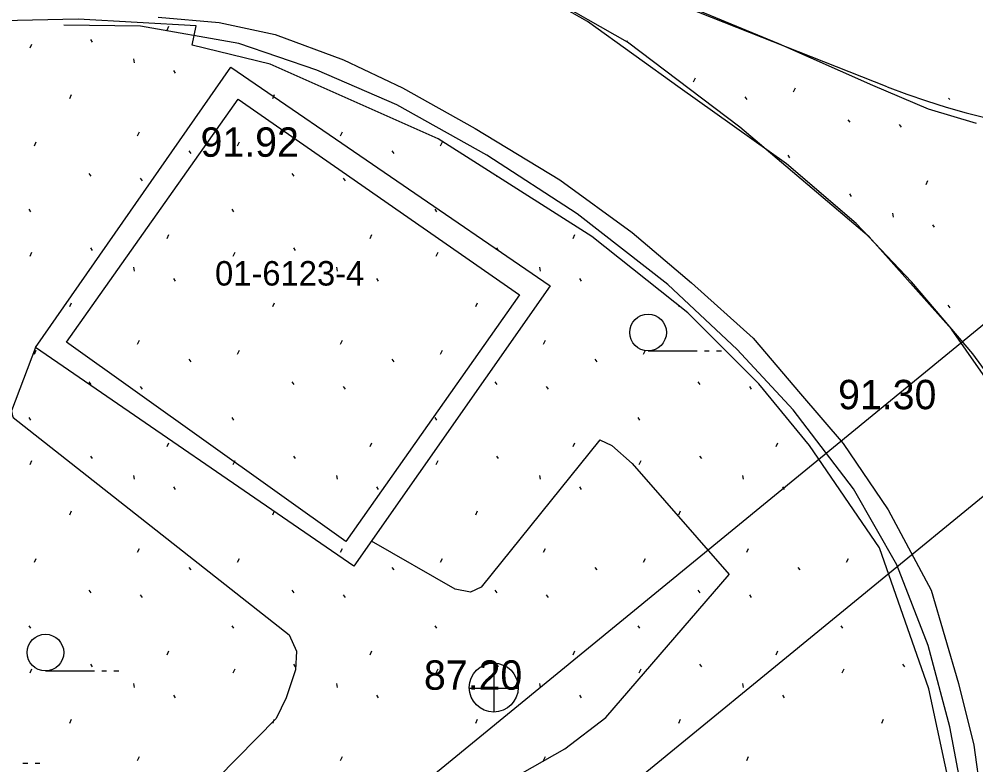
# Model space of a CAD drawing. Extents: x 412225 to 413380, y 4456471 to 4457189.
# Drawn here: x 412629.14 to 412668.22, y 4456816.59 to 4456847.07 of the extents above; entities that cross this region are included whole.
import ezdxf

# ---------------------------------------------------------------- set-up
doc = ezdxf.new("R2010")
doc.units = 0
for name, color, linetype in [('0_HALİHAZIR', 7, 'Continuous'), ('0_KADASTRO', 7, 'Continuous'), ('Level 41', 7, 'Continuous'), ('Level 62', 7, 'Continuous'), ('Level 8', 7, 'Continuous')]:
    doc.layers.add(name, color=color, linetype=linetype)

msp = doc.modelspace()

# ---------------------------------------------------------------- linework, layer by layer
at = {"layer": '0_HALİHAZIR'}
for p, q in [((412654.832, 4456833.512), (412656.832, 4456833.512)), ((412657.132, 4456833.512), (412657.332, 4456833.512)), ((412657.632, 4456833.512), (412657.832, 4456833.512)), ((412630.214, 4456820.429), (412632.214, 4456820.429)), ((412632.514, 4456820.429), (412632.714, 4456820.429)), ((412633.014, 4456820.429), (412633.214, 4456820.429)), ((412648.542, 4456818.742), (412648.542, 4456820.742)), ((412647.522, 4456819.732), (412649.522, 4456819.732)), ((412629.291, 4456816.662), (412629.491, 4456816.662)), ((412629.791, 4456816.662), (412629.991, 4456816.662))]:
    msp.add_line(p, q, dxfattribs=at)
for points in [[(412669.677, 4456831.226), (412668.1, 4456833.389), (412665.592, 4456836.327), (412663.338, 4456838.71), (412660.492, 4456841.151), (412656.14, 4456844.243), (412652.353, 4456846.965), (412647.413, 4456849.769)], [(412655.642, 4456847.95), (412660.156, 4456846.077), (412663.995, 4456844.374), (412666.277, 4456843.405), (412668.242, 4456842.809)], [(412634.822, 4456847.151), (412637.307, 4456846.924), (412639.599, 4456846.432), (412642.392, 4456845.405), (412644.808, 4456844.257), (412647.775, 4456842.591), (412651.224, 4456840.504), (412654.182, 4456838.345), (412656.611, 4456836.293), (412659.126, 4456834.029), (412661.066, 4456831.757), (412662.805, 4456829.727), (412664.637, 4456827.009), (412666.394, 4456823.731), (412667.519, 4456819.918), (412668.147, 4456817.396), (412668.717, 4456813.262)], [(412667.792, 4456812.548), (412667.684, 4456815.406), (412667.167, 4456818.144), (412666.28, 4456821.467), (412664.999, 4456824.769), (412663.228, 4456827.866), (412660.764, 4456831.101), (412658.476, 4456833.565), (412655.643, 4456836.219), (412651.936, 4456839.107), (412648.252, 4456841.502), (412644.572, 4456843.569), (412641.297, 4456844.984), (412638.109, 4456846.071), (412634.105, 4456846.785), (412630.965, 4456846.821)], [(412629.814, 4456833.643), (412628.832, 4456831.065), (412628.868, 4456830.851), (412628.902, 4456830.786), (412640.176, 4456821.911), (412640.466, 4456821.242), (412640.428, 4456820.469), (412640.05, 4456819.329), (412639.635, 4456818.485), (412622.042, 4456800.596), (412615.623, 4456806.797), (412612.828, 4456810.241), (412609.854, 4456814.685), (412608.389, 4456818.164), (412607.724, 4456820.932), (412607.515, 4456822.869), (412607.405, 4456823.607), (412607.004, 4456824.094), (412606.722, 4456824.271), (412605.838, 4456824.415)], [(412652.858, 4456829.876), (412648.015, 4456823.855), (412647.574, 4456823.652), (412646.948, 4456823.774), (412643.529, 4456825.732)], [(412652.858, 4456829.876), (412653.353, 4456829.637), (412654.183, 4456828.905), (412658.149, 4456824.365)], [(412643.499, 4456805.627), (412641.008, 4456808.45), (412640.674, 4456808.856), (412640.67, 4456809.119), (412640.893, 4456809.566), (412646.069, 4456814.211), (412648.791, 4456815.747), (412651.432, 4456817.249), (412653.106, 4456818.522), (412658.149, 4456824.365)]]:
    msp.add_lwpolyline(points, dxfattribs=at)
msp.add_lwpolyline([(412650.832, 4456836.17), (412642.814, 4456824.711), (412629.814, 4456833.643), (412637.782, 4456845.101)], close=True, dxfattribs=at)
for centre, radius in [((412654.832, 4456834.262), 0.75), ((412630.214, 4456821.179), 0.75), ((412648.527, 4456819.75), 1)]:
    msp.add_circle(centre, radius, dxfattribs=at)
at = {"layer": '0_KADASTRO'}
for points in [[(412631.069, 4456833.866), (412638.087, 4456843.8), (412649.579, 4456835.794), (412642.489, 4456825.726)], [(412654.19, 4456815.824), (412670.548, 4456829.23), (412692.977, 4456806.46), (412679.056, 4456790.643), (412671.338, 4456798.646), (412671.035, 4456798.947), (412668.435, 4456801.538)]]:
    msp.add_lwpolyline(points, close=True, dxfattribs=at)
at = {"layer": 'Level 41'}
for p, q in [((412635.188, 4456846.617), (412635.259, 4456846.776)), ((412632.059, 4456846.233), (412632.13, 4456846.126)), ((412629.594, 4456845.888), (412629.666, 4456846.048)), ((412653.971, 4456846.14), (412653.995, 4456846.192)), ((412633.817, 4456845.442), (412633.835, 4456845.282)), ((412635.447, 4456844.972), (412635.517, 4456844.865)), ((412656.695, 4456844.502), (412656.765, 4456844.662)), ((412631.21, 4456843.828), (412631.282, 4456843.988)), ((412639.503, 4456843.828), (412639.575, 4456843.988)), ((412658.79, 4456843.886), (412658.861, 4456843.78)), ((412660.778, 4456844.094), (412660.849, 4456844.254)), ((412667.112, 4456843.843), (412667.154, 4456843.78)), ((412662.998, 4456842.957), (412663.069, 4456842.85)), ((412665.097, 4456842.765), (412665.168, 4456842.658)), ((412633.982, 4456842.298), (412634.052, 4456842.458)), ((412642.275, 4456842.298), (412642.345, 4456842.458)), ((412629.772, 4456841.89), (412629.843, 4456842.05)), ((412638.065, 4456841.89), (412638.136, 4456842.05)), ((412646.358, 4456841.89), (412646.429, 4456842.05)), ((412636.077, 4456841.682), (412636.148, 4456841.576)), ((412644.37, 4456841.682), (412644.441, 4456841.576)), ((412660.542, 4456841.504), (412660.613, 4456841.397)), ((412631.992, 4456840.753), (412632.063, 4456840.646)), ((412640.285, 4456840.753), (412640.356, 4456840.646)), ((412634.091, 4456840.561), (412634.162, 4456840.454)), ((412642.384, 4456840.561), (412642.455, 4456840.454)), ((412648.644, 4456840.655), (412648.649, 4456840.646)), ((412666.194, 4456840.311), (412666.265, 4456840.47)), ((412663.065, 4456839.927), (412663.136, 4456839.82)), ((412629.536, 4456839.3), (412629.607, 4456839.193)), ((412637.829, 4456839.3), (412637.9, 4456839.193)), ((412646.122, 4456839.3), (412646.193, 4456839.193)), ((412664.823, 4456839.136), (412664.841, 4456838.976)), ((412666.453, 4456838.666), (412666.523, 4456838.559)), ((412635.188, 4456838.107), (412635.259, 4456838.266)), ((412643.481, 4456838.107), (412643.552, 4456838.266)), ((412651.774, 4456838.107), (412651.845, 4456838.266)), ((412632.059, 4456837.723), (412632.13, 4456837.616)), ((412640.352, 4456837.723), (412640.423, 4456837.616)), ((412648.645, 4456837.723), (412648.716, 4456837.616)), ((412629.594, 4456837.378), (412629.666, 4456837.538)), ((412637.887, 4456837.378), (412637.959, 4456837.538)), ((412646.18, 4456837.378), (412646.252, 4456837.538)), ((412633.817, 4456836.932), (412633.835, 4456836.772)), ((412642.11, 4456836.932), (412642.128, 4456836.772)), ((412650.403, 4456836.932), (412650.421, 4456836.772)), ((412635.447, 4456836.462), (412635.517, 4456836.355)), ((412643.74, 4456836.462), (412643.81, 4456836.355)), ((412652.033, 4456836.462), (412652.103, 4456836.355)), ((412631.21, 4456835.318), (412631.282, 4456835.478)), ((412639.503, 4456835.318), (412639.575, 4456835.478)), ((412647.796, 4456835.318), (412647.868, 4456835.478)), ((412656.089, 4456835.318), (412656.103, 4456835.348)), ((412667.083, 4456835.376), (412667.154, 4456835.27)), ((412633.982, 4456833.788), (412634.052, 4456833.948)), ((412642.275, 4456833.788), (412642.345, 4456833.948)), ((412650.568, 4456833.788), (412650.638, 4456833.948)), ((412629.772, 4456833.38), (412629.843, 4456833.54)), ((412638.065, 4456833.38), (412638.136, 4456833.54)), ((412646.358, 4456833.38), (412646.429, 4456833.54)), ((412654.651, 4456833.38), (412654.722, 4456833.54)), ((412636.077, 4456833.172), (412636.148, 4456833.066)), ((412644.37, 4456833.172), (412644.441, 4456833.066)), ((412652.663, 4456833.172), (412652.734, 4456833.066)), ((412631.992, 4456832.243), (412632.063, 4456832.136)), ((412640.285, 4456832.243), (412640.356, 4456832.136)), ((412648.578, 4456832.243), (412648.649, 4456832.136)), ((412656.871, 4456832.243), (412656.942, 4456832.136)), ((412634.091, 4456832.051), (412634.162, 4456831.944)), ((412642.384, 4456832.051), (412642.455, 4456831.944)), ((412650.677, 4456832.051), (412650.748, 4456831.944)), ((412658.97, 4456832.051), (412659.041, 4456831.944)), ((412629.536, 4456830.79), (412629.607, 4456830.683)), ((412637.829, 4456830.79), (412637.9, 4456830.683)), ((412646.122, 4456830.79), (412646.193, 4456830.683)), ((412654.415, 4456830.79), (412654.486, 4456830.683)), ((412635.188, 4456829.597), (412635.259, 4456829.756)), ((412643.481, 4456829.597), (412643.552, 4456829.756)), ((412651.774, 4456829.597), (412651.845, 4456829.756)), ((412660.067, 4456829.597), (412660.138, 4456829.756)), ((412629.594, 4456828.868), (412629.666, 4456829.028)), ((412632.059, 4456829.213), (412632.13, 4456829.106)), ((412637.887, 4456828.868), (412637.959, 4456829.028)), ((412640.352, 4456829.213), (412640.423, 4456829.106)), ((412646.18, 4456828.868), (412646.252, 4456829.028)), ((412648.645, 4456829.213), (412648.716, 4456829.106)), ((412654.473, 4456828.868), (412654.545, 4456829.028)), ((412656.938, 4456829.213), (412657.009, 4456829.106)), ((412633.817, 4456828.422), (412633.835, 4456828.262)), ((412642.11, 4456828.422), (412642.128, 4456828.262)), ((412650.403, 4456828.422), (412650.421, 4456828.262)), ((412658.696, 4456828.422), (412658.714, 4456828.262)), ((412635.447, 4456827.952), (412635.517, 4456827.845)), ((412643.74, 4456827.952), (412643.81, 4456827.845)), ((412652.033, 4456827.952), (412652.103, 4456827.845)), ((412660.326, 4456827.952), (412660.396, 4456827.845)), ((412631.21, 4456826.808), (412631.282, 4456826.968)), ((412639.503, 4456826.808), (412639.575, 4456826.968)), ((412647.796, 4456826.808), (412647.868, 4456826.968)), ((412656.089, 4456826.808), (412656.161, 4456826.968)), ((412633.982, 4456825.278), (412634.052, 4456825.438)), ((412642.275, 4456825.278), (412642.345, 4456825.438)), ((412650.568, 4456825.278), (412650.638, 4456825.438)), ((412658.861, 4456825.278), (412658.931, 4456825.438)), ((412629.772, 4456824.87), (412629.843, 4456825.03)), ((412638.065, 4456824.87), (412638.136, 4456825.03)), ((412646.358, 4456824.87), (412646.429, 4456825.03)), ((412654.651, 4456824.87), (412654.722, 4456825.03)), ((412662.944, 4456824.87), (412663.015, 4456825.03)), ((412636.077, 4456824.662), (412636.148, 4456824.556)), ((412644.37, 4456824.662), (412644.441, 4456824.556)), ((412652.663, 4456824.662), (412652.734, 4456824.556)), ((412660.956, 4456824.662), (412661.027, 4456824.556)), ((412631.992, 4456823.733), (412632.063, 4456823.626)), ((412640.285, 4456823.733), (412640.356, 4456823.626)), ((412648.578, 4456823.733), (412648.649, 4456823.626)), ((412656.871, 4456823.733), (412656.942, 4456823.626)), ((412634.091, 4456823.541), (412634.162, 4456823.434)), ((412642.384, 4456823.541), (412642.455, 4456823.434)), ((412650.677, 4456823.541), (412650.748, 4456823.434)), ((412658.97, 4456823.541), (412659.041, 4456823.434)), ((412629.536, 4456822.28), (412629.607, 4456822.173)), ((412637.829, 4456822.28), (412637.9, 4456822.173)), ((412646.122, 4456822.28), (412646.193, 4456822.173)), ((412654.415, 4456822.28), (412654.486, 4456822.173)), ((412662.708, 4456822.28), (412662.779, 4456822.173)), ((412635.188, 4456821.087), (412635.259, 4456821.246)), ((412643.481, 4456821.087), (412643.552, 4456821.246)), ((412651.774, 4456821.087), (412651.845, 4456821.246)), ((412660.067, 4456821.087), (412660.138, 4456821.246)), ((412629.594, 4456820.358), (412629.666, 4456820.518)), ((412632.059, 4456820.703), (412632.13, 4456820.596)), ((412637.887, 4456820.358), (412637.959, 4456820.518)), ((412640.352, 4456820.703), (412640.423, 4456820.596)), ((412646.18, 4456820.358), (412646.252, 4456820.518)), ((412648.645, 4456820.703), (412648.716, 4456820.596)), ((412654.473, 4456820.358), (412654.545, 4456820.518)), ((412656.938, 4456820.703), (412657.009, 4456820.596)), ((412662.766, 4456820.358), (412662.838, 4456820.518)), ((412665.231, 4456820.703), (412665.302, 4456820.596)), ((412633.817, 4456819.912), (412633.835, 4456819.752)), ((412642.11, 4456819.912), (412642.128, 4456819.752)), ((412650.403, 4456819.912), (412650.421, 4456819.752)), ((412658.696, 4456819.912), (412658.714, 4456819.752)), ((412635.447, 4456819.442), (412635.517, 4456819.335)), ((412643.74, 4456819.442), (412643.81, 4456819.335)), ((412652.033, 4456819.442), (412652.103, 4456819.335)), ((412660.326, 4456819.442), (412660.396, 4456819.335)), ((412631.21, 4456818.298), (412631.282, 4456818.458)), ((412639.503, 4456818.298), (412639.575, 4456818.458)), ((412647.796, 4456818.298), (412647.868, 4456818.458)), ((412656.089, 4456818.298), (412656.161, 4456818.458)), ((412664.382, 4456818.298), (412664.454, 4456818.458)), ((412633.982, 4456816.768), (412634.052, 4456816.928)), ((412642.275, 4456816.768), (412642.345, 4456816.928)), ((412650.568, 4456816.768), (412650.638, 4456816.928)), ((412658.861, 4456816.768), (412658.931, 4456816.928))]:
    msp.add_line(p, q, dxfattribs=at)
at = {"layer": 'Level 62'}
for p, q in [((412664.604, 4456844.304), (412642.404, 4456853.067)), ((412653.989, 4456846.13), (412648.748, 4456849.117)), ((412658.579, 4456842.652), (412653.989, 4456846.13)), ((412663.86, 4456838.173), (412658.579, 4456842.652)), ((412667.233, 4456834.392), (412663.86, 4456838.173)), ((412670.303, 4456829.971), (412667.233, 4456834.392))]:
    msp.add_line(p, q, dxfattribs=at)
for points in [[(412636.366, 4456846.799), (412631.55, 4456847.064), (412627.194, 4456846.974), (412624.434, 4456846.592), (412620.328, 4456845.197), (412617.321, 4456843.794), (412614.55, 4456842.046), (412611.373, 4456839.007), (412609.294, 4456836.044), (412607.301, 4456832.111), (412606.231, 4456828.608), (412605.615, 4456824.958), (412605.6, 4456821.774)], [(412636.366, 4456846.799), (412631.55, 4456847.064), (412627.194, 4456846.974), (412624.434, 4456846.592), (412620.328, 4456845.197), (412617.321, 4456843.794), (412614.55, 4456842.046), (412611.373, 4456839.007), (412609.294, 4456836.044), (412607.301, 4456832.111), (412606.231, 4456828.608), (412605.615, 4456824.958), (412605.6, 4456821.774)], [(412667.093, 4456803.688), (412667.462, 4456810.627), (412667.327, 4456814.94), (412666.309, 4456819.695), (412664.291, 4456825.461), (412661.434, 4456829.638), (412659.355, 4456832.156), (412656.46, 4456835.064), (412652.536, 4456838.183), (412646.255, 4456842.172), (412639.4, 4456845.232), (412636.204, 4456846.004), (412636.366, 4456846.799)]]:
    msp.add_lwpolyline(points, dxfattribs=at)
msp.add_arc((412675.435, 4456871.744), 29.5, 248.459, 300.6031, dxfattribs=at)
at = {"layer": 'Level 8'}
msp.add_lwpolyline([(412706.1, 4457175.965), (412751.217, 4457041.463), (412764.575, 4457001.385), (412790.361, 4457003.87), (412821.118, 4456953.851), (412699.954, 4456860.338), (412631.485, 4456804.219), (412585.777, 4456849.927), (412523.439, 4456912.266), (412460.309, 4456974.831), (412403.512, 4457031.625), (412342.192, 4457092.946), (412287.774, 4457146.913), (412253.259, 4457181.199)], dxfattribs=at)

# ---------------------------------------------------------------- texts
at = {"layer": '0_HALİHAZIR'}
for s, p in [('91.92', (412636.552, 4456841.442)), ('91.30', (412662.596, 4456831.125)), ('87.20', (412645.678, 4456819.662))]:
    msp.add_text(s, height=1.2, dxfattribs=at).set_placement(p)
at = {"layer": '0_KADASTRO'}
msp.add_text('01-6123-4', height=1, dxfattribs=at).set_placement((412637.143, 4456836.179))
msp.add_text('01-6123-4', height=1, dxfattribs=at).set_placement((412637.143, 4456836.179))

doc.saveas('drawing.dxf')
